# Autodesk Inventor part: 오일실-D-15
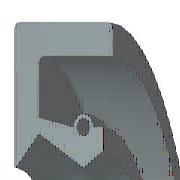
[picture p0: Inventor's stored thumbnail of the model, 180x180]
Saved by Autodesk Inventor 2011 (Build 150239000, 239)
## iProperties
IsCustomPart: 0
Company: 한국ATC센터
Created: 2014-12
Part Number: 오일실-D-15
Material: 고무
Description: 오일-실
Document SubType Name: Modeling
Standard: KS B 2804
Designer: KYOUNG IL JANG
Standards Organization: KS
Language: ko-KR
Size Designation: D - 15 30 7
Categories: <MemberInstance><Categories><Category DisplayName="샤프트 부품" InternalName="7f7aeb1f-a693-4053-b835-cee3144e0d98" Mnemonic="SHFT"><Category DisplayName="실링" Intern
Density: 0.93 g/cm^3
Mass: 1.95008 g
Surface Area: 27.8517 cm^2
Volume: 2.09686 cm^3
Author: KYOUNG IL JANG
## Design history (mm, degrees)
revolve "본체" stored, may be unused: angle "d17" = 90 deg
revolve "스프링1" stored, may be unused: angle "d18" = 90 deg
body "Solid1"
sketch "스케치1"
  geometry: L1 (0, 15)-(7, 15); L2 (7, 13.25)-(1.75, 13.25); L3 (1.75, 9.25)-(4.9, 7.5); L4 (4.9, 7.5)-(0, 7.5); L5 (0, 0)-(9.586, 0) reference; L6 (4.9, 7.5)-(6.3, 8.375); L7 (0, 18)-(0, -3) reference; L8 (-1.941, 0)-(11.507, 0) reference; L9 (4.2, 9.6)-(1.75, 10.09); L10 (1.75, 10.09)-(1.75, 13.25); L11 (0, 15)-(0, 7.588); L12 (4.9, 7.5)-(0, 7.5); L13 (1.75, 9.25)-(0.152, 7.528); L14 (7, 15)-(7, 13.25); L15 (5.6, 9.6)-(6.3, 9.6); L16 (6.3, 9.6)-(6.3, 8.375); C1 r 0.455 at (4.9, 9.6); A1 r 0.7 centre (4.9, 9.6) between (5.6, 9.6) and (4.2, 9.6); A2 r 0.088 centre (0.088, 7.588) between (0, 7.588) and (0.152, 7.528); 1 further point
  constraints: 28 end point, 5 horizontal alignment, 5 point on line, 4 point on circle, 4 vertical alignment, 3 centre point, 3 tangent, 2 collinear, 2 horizontal, 2 perpendicular, 1 coincident, 1 parallel
  dimensions: "d0" = 30 diameter of L1 L5 (= SD2); "d1" = 1.75 distance of L1.end L2.start (= SD); "d2" = 0.91 diameter of C1 (= SPDI); "d3" = 1.4 diameter of A1 (= SPDA); "d4" = 15 diameter of L3.end L5 (= NND); "d5" = 18.5 diameter of L3.start L5 (= TKDM); "d7" = 20.18 diameter of L9.end L5 (= TKDM + 0.24 x SWDT); "d8" = 1.75 distance between parallel lines of L11 L10 (= SD); "d9" = 4.9 distance from line of L11 C1.centre (= SPDST); "d10" = 19.2 diameter of C1.centre L5 (= HLDM); "d11" = 0.0875 radius of A2 (= 0.25 x LAB); "d12" = 6.3 distance between parallel lines of L11 L16 (= SDI); "d13" = 16.75 diameter of L6.end L5 (= ABDM); "d14" = 7 distance from line of L11 L1.end (= SWDT)
fillet "모깎기1" dims "d6" = 0.3 (= RR)
other parameters: "SD2" = 30 [user parameter; used in 1 equation term], "SWDT" = 7 [user parameter; used in 2 equation terms], "RR" = 0.3 [user parameter; used in 1 equation term], "SD" = 1.75 [user parameter; used in 2 equation terms], "NND" = 15 [user parameter; used in 1 equation term], "SPDA" = 1.4 [user parameter; used in 1 equation term], "SPDI" = 0.91 [user parameter; used in 1 equation term], "TKDM" = 18.5 [user parameter; used in 2 equation terms], "HLDM" = 19.2 [user parameter; used in 1 equation term], "ABDM" = 16.75 [user parameter; used in 1 equation term], "SDI" = 6.3 [user parameter; used in 1 equation term], "SPDST" = 4.9 [user parameter; used in 1 equation term], "LAB" = 0.35 [user parameter; used in 1 equation term], "d15" = 0, "d16" = 0, "d19" = 0
